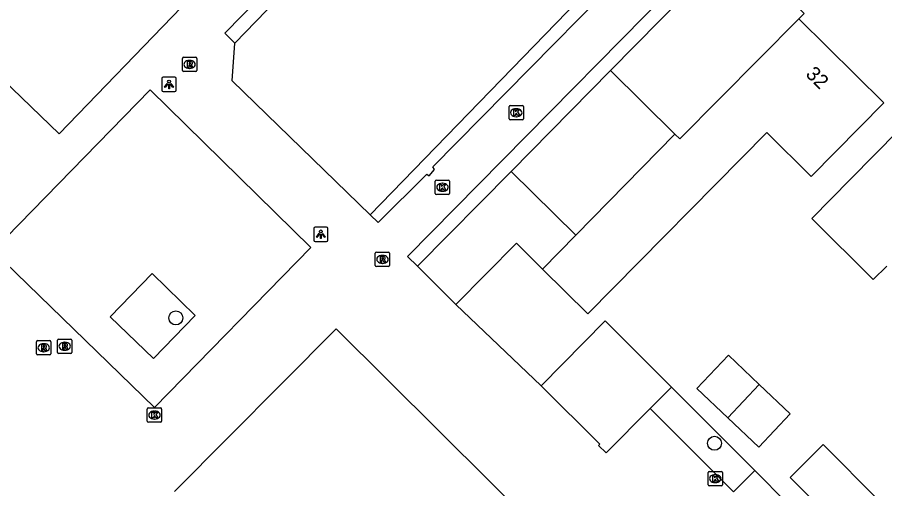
# Model space of a CAD drawing. Extents: x 161772 to 163123, y 383092 to 383917.
# Drawn here: x 162073.6 to 162134.1, y 383301.5 to 383334.4 of the extents above; entities that cross this region are included whole.
import ezdxf

# ---------------------------------------------------------------- set-up
doc = ezdxf.new("R2010")
doc.units = 0
for name, color, linetype in [('IMGEO_Boom', 7, 'Continuous'), ('IMGEO_Erf', 7, 'Continuous'), ('IMGEO_Groenvoorziening', 7, 'Continuous'), ('IMGEO_Kolk', 7, 'Continuous'), ('IMGEO_Lichtpunt', 7, 'Continuous'), ('IMGEO_Pand', 7, 'Continuous'), ('IMGEO_Pand_nummerreeks', 7, 'Continuous'), ('IMGEO_Rijbaan_lokaal_open', 7, 'Continuous'), ('IMGEO_Rioolput', 7, 'Continuous'), ('IMGEO_Voetpad_open', 7, 'Continuous')]:
    doc.layers.add(name, color=color, linetype=linetype)

msp = doc.modelspace()

# ---------------------------------------------------------------- linework, layer by layer
at = {"layer": 'IMGEO_Boom'}
for centre in [(162084.661, 383313.418), (162122.266, 383304.673)]:
    msp.add_circle(centre, 0.489, dxfattribs=at)
at = {"layer": 'IMGEO_Erf'}
msp.add_lwpolyline([(162108.065, 383323.626), (162115.011, 383330.687)], dxfattribs=at)
at = {"layer": 'IMGEO_Groenvoorziening'}
msp.add_lwpolyline([(162125.085, 383302.767), (162119.266, 383308.601)], dxfattribs=at)
at = {"layer": 'IMGEO_Kolk'}
for p, q in [((162107.927, 383327.31), (162107.927, 383328.162)), ((162108.002, 383328.236), (162108.854, 383328.236)), ((162108.415, 383328.016), (162108.44, 383328.016)), ((162108.928, 383328.162), (162108.928, 383327.31)), ((162108.438, 383327.456), (162108.413, 383327.456)), ((162108.854, 383327.236), (162108.002, 383327.236)), ((162102.773, 383322.104), (162102.773, 383322.956)), ((162102.848, 383323.03), (162103.7, 383323.03)), ((162103.261, 383322.81), (162103.286, 383322.81)), ((162103.774, 383322.956), (162103.774, 383322.104)), ((162103.7, 383322.03), (162102.848, 383322.03)), ((162103.284, 383322.25), (162103.259, 383322.25)), ((162082.67, 383306.214), (162082.67, 383307.066)), ((162082.745, 383307.14), (162083.597, 383307.14)), ((162083.158, 383306.92), (162083.183, 383306.92)), ((162083.671, 383307.066), (162083.671, 383306.214)), ((162083.181, 383306.36), (162083.156, 383306.36)), ((162083.597, 383306.14), (162082.745, 383306.14)), ((162121.824, 383301.788), (162121.824, 383302.64)), ((162121.899, 383302.714), (162122.751, 383302.714)), ((162122.825, 383302.64), (162122.825, 383301.788)), ((162122.335, 383301.934), (162122.31, 383301.934)), ((162122.312, 383302.494), (162122.337, 383302.494)), ((162122.751, 383301.714), (162121.899, 383301.714))]:
    msp.add_line(p, q, dxfattribs=at)
for points in [[(162107.927, 383327.31), (162107.927, 383328.162)], [(162108.002, 383328.236), (162108.854, 383328.236)], [(162108.928, 383328.162), (162108.928, 383327.31)], [(162108.248, 383327.936), (162108.371, 383327.936), (162108.371, 383327.785), (162108.501, 383327.936), (162108.665, 383327.936), (162108.519, 383327.785), (162108.672, 383327.536), (162108.52, 383327.536), (162108.435, 383327.7), (162108.371, 383327.633), (162108.371, 383327.536), (162108.248, 383327.536), (162108.248, 383327.936)], [(162108.854, 383327.236), (162108.002, 383327.236)], [(162102.773, 383322.104), (162102.773, 383322.956)], [(162102.848, 383323.03), (162103.7, 383323.03)], [(162103.094, 383322.73), (162103.217, 383322.73), (162103.217, 383322.579), (162103.347, 383322.73), (162103.511, 383322.73), (162103.365, 383322.579), (162103.518, 383322.33), (162103.366, 383322.33), (162103.281, 383322.494), (162103.217, 383322.427), (162103.217, 383322.33), (162103.094, 383322.33), (162103.094, 383322.73)], [(162103.774, 383322.956), (162103.774, 383322.104)], [(162103.7, 383322.03), (162102.848, 383322.03)], [(162082.67, 383306.214), (162082.67, 383307.066)], [(162082.745, 383307.14), (162083.597, 383307.14)], [(162082.991, 383306.84), (162083.114, 383306.84), (162083.114, 383306.689), (162083.244, 383306.84), (162083.408, 383306.84), (162083.262, 383306.689), (162083.415, 383306.44), (162083.263, 383306.44), (162083.178, 383306.604), (162083.114, 383306.537), (162083.114, 383306.44), (162082.991, 383306.44), (162082.991, 383306.84)], [(162083.671, 383307.066), (162083.671, 383306.214)], [(162083.597, 383306.14), (162082.745, 383306.14)], [(162121.824, 383301.788), (162121.824, 383302.64)], [(162121.899, 383302.714), (162122.751, 383302.714)], [(162122.825, 383302.64), (162122.825, 383301.788)], [(162122.145, 383302.414), (162122.268, 383302.414), (162122.268, 383302.263), (162122.398, 383302.414), (162122.562, 383302.414), (162122.416, 383302.263), (162122.569, 383302.014), (162122.417, 383302.014), (162122.332, 383302.178), (162122.268, 383302.111), (162122.268, 383302.014), (162122.145, 383302.014), (162122.145, 383302.414)], [(162122.751, 383301.714), (162121.899, 383301.714)]]:
    msp.add_lwpolyline(points, dxfattribs=at)
for centre, start, end in [((162108.004, 383328.16), 91.55205, 178.44795), ((162108.004, 383328.16), 91.55205, 178.44795), ((162108.852, 383328.16), 1.55205, 88.44795), ((162108.852, 383328.16), 1.55205, 88.44795), ((162108.004, 383327.312), 181.55205, 268.44795), ((162108.004, 383327.312), 181.55205, 268.44795), ((162108.852, 383327.312), 271.55205, 358.44795), ((162108.852, 383327.312), 271.55205, 358.44795), ((162102.85, 383322.954), 91.55205, 178.44795), ((162102.85, 383322.954), 91.55205, 178.44795), ((162103.698, 383322.954), 1.55205, 88.44795), ((162103.698, 383322.954), 1.55205, 88.44795), ((162102.85, 383322.106), 181.55205, 268.44795), ((162102.85, 383322.106), 181.55205, 268.44795), ((162103.698, 383322.106), 271.55205, 358.44795), ((162103.698, 383322.106), 271.55205, 358.44795), ((162082.747, 383307.064), 91.55205, 178.44795), ((162082.747, 383307.064), 91.55205, 178.44795), ((162083.595, 383307.064), 1.55205, 88.44795), ((162083.595, 383307.064), 1.55205, 88.44795), ((162082.747, 383306.216), 181.55205, 268.44795), ((162082.747, 383306.216), 181.55205, 268.44795), ((162083.595, 383306.216), 271.55205, 358.44795), ((162083.595, 383306.216), 271.55205, 358.44795), ((162121.901, 383302.638), 91.55205, 178.44795), ((162121.901, 383302.638), 91.55205, 178.44795), ((162122.749, 383302.638), 1.55205, 88.44795), ((162122.749, 383302.638), 1.55205, 88.44795), ((162121.901, 383301.79), 181.55205, 268.44795), ((162121.901, 383301.79), 181.55205, 268.44795), ((162122.749, 383301.79), 271.55205, 358.44795), ((162122.749, 383301.79), 271.55205, 358.44795)]:
    msp.add_arc(centre, 0.0765, start, end, dxfattribs=at)
for centre, major_axis, ratio, start_param, end_param in [((162108.414, 383327.736), (-0.387, 0.002), 0.722429, 4.712389, 7.853982), ((162108.439, 383327.736), (-0.39, 0.002), 0.717154, 1.570796, 4.712389), ((162103.26, 383322.53), (-0.387, 0.002), 0.722429, 4.712389, 7.853982), ((162103.285, 383322.53), (-0.39, 0.002), 0.717154, 1.570796, 4.712389), ((162083.157, 383306.64), (-0.387, 0.002), 0.722429, 4.712389, 7.853982), ((162083.182, 383306.64), (-0.39, 0.002), 0.717154, 1.570796, 4.712389), ((162122.311, 383302.214), (-0.387, 0.002), 0.722429, 4.712389, 7.853982), ((162122.336, 383302.214), (-0.39, 0.002), 0.717154, 1.570796, 4.712389)]:
    msp.add_ellipse(centre, major_axis=major_axis, ratio=ratio, start_param=start_param, end_param=end_param, dxfattribs=at)
at = {"layer": 'IMGEO_Lichtpunt'}
for p, q in [((162083.687, 383330.115), (162083.687, 383329.308)), ((162083.687, 383330.115), (162083.687, 383329.308)), ((162084.589, 383330.21), (162083.781, 383330.21)), ((162084.589, 383330.21), (162083.781, 383330.21)), ((162084.683, 383329.308), (162084.683, 383330.115)), ((162084.683, 383329.308), (162084.683, 383330.115)), ((162083.781, 383329.214), (162084.589, 383329.214)), ((162083.781, 383329.214), (162084.589, 383329.214)), ((162094.286, 383319.656), (162094.286, 383318.849)), ((162094.286, 383319.656), (162094.286, 383318.849)), ((162095.188, 383319.751), (162094.38, 383319.751)), ((162095.188, 383319.751), (162094.38, 383319.751)), ((162095.282, 383318.849), (162095.282, 383319.656)), ((162095.282, 383318.849), (162095.282, 383319.656)), ((162094.38, 383318.755), (162095.188, 383318.755)), ((162094.38, 383318.755), (162095.188, 383318.755))]:
    msp.add_line(p, q, dxfattribs=at)
for points in [[(162084.061, 383329.779), (162084.1, 383329.751), (162083.912, 383329.489), (162083.874, 383329.516), (162084.061, 383329.779)], [(162084.273, 383329.751), (162084.311, 383329.778), (162084.498, 383329.516), (162084.459, 383329.488), (162084.273, 383329.751)], [(162084.163, 383329.731), (162084.21, 383329.731), (162084.21, 383329.409), (162084.163, 383329.409), (162084.163, 383329.731)], [(162094.66, 383319.32), (162094.699, 383319.292), (162094.511, 383319.03), (162094.473, 383319.057), (162094.66, 383319.32)], [(162094.762, 383319.272), (162094.809, 383319.272), (162094.809, 383318.95), (162094.762, 383318.95), (162094.762, 383319.272)], [(162094.872, 383319.292), (162094.91, 383319.319), (162095.097, 383319.057), (162095.058, 383319.029), (162094.872, 383319.292)]]:
    msp.add_lwpolyline(points, dxfattribs=at)
for centre in [(162084.186, 383329.913), (162094.785, 383319.454)]:
    msp.add_circle(centre, 0.0994, dxfattribs=at)
for centre, start, end in [((162083.781, 383330.115), 90, 180), ((162083.781, 383330.115), 90, 180), ((162084.589, 383330.115), 0, 90), ((162084.589, 383330.115), 0, 90), ((162083.781, 383329.308), 180, 270), ((162083.781, 383329.308), 180, 270), ((162084.589, 383329.308), 270, 0), ((162084.589, 383329.308), 270, 360), ((162094.38, 383319.656), 90, 180), ((162094.38, 383319.656), 90, 180), ((162095.188, 383319.656), 0, 90), ((162095.188, 383319.656), 0, 90), ((162094.38, 383318.849), 180, 270), ((162094.38, 383318.849), 180, 270), ((162095.188, 383318.849), 270, 0), ((162095.188, 383318.849), 270, 360)]:
    msp.add_arc(centre, 0.0946, start, end, dxfattribs=at)
at = {"layer": 'IMGEO_Pand'}
for points in [[(162088.781, 383332.589), (162104.911, 383349.231), (162115.766, 383338.708)], [(162115.011, 383330.687), (162123.664, 383339.476), (162128.52, 383334.645), (162128.16, 383334.283)], [(162115.766, 383338.708), (162098.225, 383320.611)], [(162128.16, 383334.283), (162134.092, 383328.422), (162129.012, 383323.283), (162125.92, 383326.354), (162113.418, 383313.706), (162110.271, 383316.822)], [(162128.16, 383334.283), (162119.841, 383325.918), (162119.51, 383326.245)], [(162098.225, 383320.611), (162088.594, 383329.946), (162088.781, 383332.589)], [(162119.51, 383326.245), (162115.011, 383330.687)], [(162134.301, 383317.03), (162133.351, 383316.108), (162129.054, 383320.347), (162131.763, 383323.094), (162136.795, 383328.196), (162141.151, 383323.9), (162141.014, 383323.761)], [(162112.592, 383319.189), (162119.51, 383326.245)], [(162101.529, 383317.021), (162108.065, 383323.626)], [(162112.592, 383319.189), (162108.065, 383323.626)], [(162110.271, 383316.822), (162112.592, 383319.189)], [(162110.271, 383316.822), (162108.445, 383318.63), (162104.216, 383314.348)], [(162101.529, 383317.021), (162104.216, 383314.348)], [(162110.161, 383308.679), (162114.631, 383313.211), (162119.266, 383308.601)], [(162113.782, 383294.862), (162095.853, 383312.658), (162084.572, 383301.309)], [(162123.197, 383306.442), (162121.038, 383308.485), (162123.238, 383310.81), (162125.398, 383308.767)], [(162110.161, 383308.679), (162114.271, 383304.622), (162114.18, 383304.529), (162114.711, 383304.006), (162117.787, 383307.109)], [(162119.266, 383308.601), (162117.787, 383307.109)], [(162125.398, 383308.767), (162127.557, 383306.724), (162125.357, 383304.399), (162123.197, 383306.442)], [(162125.398, 383308.767), (162123.197, 383306.442)], [(162131.74, 383298.082), (162127.54, 383302.293), (162129.848, 383304.595), (162133.741, 383300.691), (162133.453, 383300.404), (162133.743, 383300.114)]]:
    msp.add_lwpolyline(points, dxfattribs=at)
at = {"layer": 'IMGEO_Rijbaan_lokaal_open'}
for points in [[(162111.39, 383357.056), (162088.084, 383333.272), (162088.781, 383332.589)], [(162098.225, 383320.611), (162098.776, 383320.077), (162102.187, 383323.44), (162102.34, 383323.339), (162102.713, 383323.781), (162102.606, 383323.956), (162121.251, 383342.87)], [(162125.72, 383342.934), (162100.83, 383317.698), (162101.529, 383317.021)], [(162072.586, 383330.051), (162076.509, 383326.257), (162085.05, 383335.095)], [(162082.872, 383329.333), (162071.894, 383318.107), (162083.161, 383307.175), (162094.093, 383318.339), (162082.872, 383329.333)], [(162104.216, 383314.348), (162110.161, 383308.679)], [(162117.787, 383307.109), (162123.599, 383301.284), (162125.085, 383302.767)], [(162125.085, 383302.767), (162127.351, 383300.496)]]:
    msp.add_lwpolyline(points, dxfattribs=at)
at = {"layer": 'IMGEO_Rioolput'}
for p, q in [((162085.195, 383331.6), (162086.047, 383331.6)), ((162085.12, 383330.674), (162085.12, 383331.526)), ((162085.608, 383331.38), (162085.633, 383331.38)), ((162086.121, 383331.526), (162086.121, 383330.674)), ((162086.047, 383330.6), (162085.195, 383330.6)), ((162085.631, 383330.82), (162085.606, 383330.82)), ((162098.586, 383317.079), (162098.586, 383317.931)), ((162098.661, 383318.005), (162099.513, 383318.005)), ((162099.074, 383317.785), (162099.099, 383317.785)), ((162099.587, 383317.931), (162099.587, 383317.079)), ((162099.097, 383317.225), (162099.072, 383317.225)), ((162099.513, 383317.005), (162098.661, 383317.005)), ((162074.935, 383310.911), (162074.935, 383311.763)), ((162075.01, 383311.837), (162075.862, 383311.837)), ((162075.423, 383311.617), (162075.448, 383311.617)), ((162075.936, 383311.763), (162075.936, 383310.911)), ((162076.403, 383311.016), (162076.403, 383311.868)), ((162076.478, 383311.942), (162077.33, 383311.942)), ((162076.891, 383311.722), (162076.916, 383311.722)), ((162077.404, 383311.868), (162077.404, 383311.016)), ((162075.446, 383311.057), (162075.421, 383311.057)), ((162076.914, 383311.162), (162076.889, 383311.162)), ((162075.862, 383310.837), (162075.01, 383310.837)), ((162077.33, 383310.942), (162076.478, 383310.942))]:
    msp.add_line(p, q, dxfattribs=at)
for points in [[(162085.195, 383331.6), (162086.047, 383331.6)], [(162085.12, 383330.674), (162085.12, 383331.526)], [(162085.709, 383331.298), (162085.457, 383331.3), (162085.457, 383330.9)], [(162085.457, 383330.9), (162085.581, 383330.9), (162085.581, 383331.062), (162085.592, 383331.062)], [(162085.635, 383331.219), (162085.581, 383331.219), (162085.581, 383331.138)], [(162085.581, 383331.138), (162085.633, 383331.138)], [(162085.639, 383331.033), (162085.71, 383330.9), (162085.85, 383330.9), (162085.785, 383331.026)], [(162086.121, 383331.526), (162086.121, 383330.674)], [(162086.047, 383330.6), (162085.195, 383330.6)], [(162098.586, 383317.079), (162098.586, 383317.931)], [(162098.661, 383318.005), (162099.513, 383318.005)], [(162099.175, 383317.703), (162098.923, 383317.705), (162098.923, 383317.305)], [(162099.587, 383317.931), (162099.587, 383317.079)], [(162098.923, 383317.305), (162099.047, 383317.305), (162099.047, 383317.467), (162099.058, 383317.467)], [(162099.101, 383317.624), (162099.047, 383317.624), (162099.047, 383317.543)], [(162099.047, 383317.543), (162099.099, 383317.543)], [(162099.105, 383317.438), (162099.176, 383317.305), (162099.316, 383317.305), (162099.251, 383317.431)], [(162099.513, 383317.005), (162098.661, 383317.005)], [(162074.935, 383310.911), (162074.935, 383311.763)], [(162075.01, 383311.837), (162075.862, 383311.837)], [(162075.936, 383311.763), (162075.936, 383310.911)], [(162076.403, 383311.016), (162076.403, 383311.868)], [(162076.478, 383311.942), (162077.33, 383311.942)], [(162076.992, 383311.64), (162076.74, 383311.642), (162076.74, 383311.242)], [(162077.404, 383311.868), (162077.404, 383311.016)], [(162075.524, 383311.535), (162075.272, 383311.537), (162075.272, 383311.137)], [(162075.272, 383311.137), (162075.396, 383311.137), (162075.396, 383311.299), (162075.407, 383311.299)], [(162075.45, 383311.456), (162075.396, 383311.456), (162075.396, 383311.375)], [(162075.396, 383311.375), (162075.448, 383311.375)], [(162075.454, 383311.27), (162075.525, 383311.137), (162075.665, 383311.137), (162075.6, 383311.263)], [(162076.74, 383311.242), (162076.864, 383311.242), (162076.864, 383311.404), (162076.875, 383311.404)], [(162076.918, 383311.561), (162076.864, 383311.561), (162076.864, 383311.48)], [(162076.864, 383311.48), (162076.916, 383311.48)], [(162076.922, 383311.375), (162076.993, 383311.242), (162077.133, 383311.242), (162077.068, 383311.368)], [(162075.862, 383310.837), (162075.01, 383310.837)], [(162077.33, 383310.942), (162076.478, 383310.942)]]:
    msp.add_lwpolyline(points, dxfattribs=at)
for centre, radius, start, end in [((162085.197, 383331.524), 0.0765, 91.55205, 178.44795), ((162085.197, 383331.524), 0.0765, 91.55205, 178.44795), ((162086.045, 383331.524), 0.0765, 1.55205, 88.44795), ((162086.045, 383331.524), 0.0765, 1.55205, 88.44795), ((162085.591, 383331.009), 0.0533, 26.02933, 88.69889), ((162085.617, 383331.327), 0.19, 274.7715, 282.96867), ((162085.641, 383331.123), 0.0964, 77.00612, 93.18647), ((162085.655, 383331.18), 0.0378, 276.66336, 79.67722), ((162085.708, 383331.188), 0.109, 350.36119, 89.41601), ((162085.706, 383331.188), 0.112, 277.58423, 350.98172), ((162085.69, 383330.973), 0.108, 29.51342, 73.79051), ((162085.197, 383330.676), 0.0765, 181.55205, 268.44795), ((162085.197, 383330.676), 0.0765, 181.55205, 268.44795), ((162086.045, 383330.676), 0.0765, 271.55205, 358.44795), ((162086.045, 383330.676), 0.0765, 271.55205, 358.44795), ((162098.663, 383317.929), 0.0765, 91.55205, 178.44795), ((162098.663, 383317.929), 0.0765, 91.55205, 178.44795), ((162099.174, 383317.593), 0.109, 350.36119, 89.41601), ((162099.511, 383317.929), 0.0765, 1.55205, 88.44795), ((162099.511, 383317.929), 0.0765, 1.55205, 88.44795), ((162098.663, 383317.081), 0.0765, 181.55205, 268.44795), ((162098.663, 383317.081), 0.0765, 181.55205, 268.44795), ((162099.057, 383317.414), 0.0533, 26.02933, 88.69889), ((162099.083, 383317.732), 0.19, 274.7715, 282.96867), ((162099.107, 383317.528), 0.0964, 77.00612, 93.18647), ((162099.121, 383317.585), 0.0378, 276.66336, 79.67722), ((162099.172, 383317.593), 0.112, 277.58423, 350.98172), ((162099.156, 383317.378), 0.108, 29.51342, 73.79051), ((162099.511, 383317.081), 0.0765, 271.55205, 358.44795), ((162099.511, 383317.081), 0.0765, 271.55205, 358.44795), ((162075.012, 383311.761), 0.0765, 91.55205, 178.44795), ((162075.012, 383311.761), 0.0765, 91.55205, 178.44795), ((162075.86, 383311.761), 0.0765, 1.55205, 88.44795), ((162075.86, 383311.761), 0.0765, 1.55205, 88.44795), ((162076.48, 383311.866), 0.0765, 91.55205, 178.44795), ((162076.48, 383311.866), 0.0765, 91.55205, 178.44795), ((162076.991, 383311.53), 0.109, 350.36119, 89.41601), ((162077.328, 383311.866), 0.0765, 1.55205, 88.44795), ((162077.328, 383311.866), 0.0765, 1.55205, 88.44795), ((162075.406, 383311.246), 0.0533, 26.02933, 88.69889), ((162075.432, 383311.564), 0.19, 274.7715, 282.96867), ((162075.456, 383311.36), 0.0964, 77.00612, 93.18647), ((162075.47, 383311.417), 0.0378, 276.66336, 79.67722), ((162075.523, 383311.425), 0.109, 350.36119, 89.41601), ((162075.521, 383311.425), 0.112, 277.58423, 350.98172), ((162075.505, 383311.21), 0.108, 29.51342, 73.79051), ((162076.48, 383311.018), 0.0765, 181.55205, 268.44795), ((162076.48, 383311.018), 0.0765, 181.55205, 268.44795), ((162076.874, 383311.351), 0.0533, 26.02933, 88.69889), ((162076.9, 383311.669), 0.19, 274.7715, 282.96867), ((162076.924, 383311.465), 0.0964, 77.00612, 93.18647), ((162076.938, 383311.522), 0.0378, 276.66336, 79.67722), ((162076.989, 383311.53), 0.112, 277.58423, 350.98172), ((162076.973, 383311.315), 0.108, 29.51342, 73.79051), ((162077.328, 383311.018), 0.0765, 271.55205, 358.44795), ((162077.328, 383311.018), 0.0765, 271.55205, 358.44795), ((162075.012, 383310.913), 0.0765, 181.55205, 268.44795), ((162075.012, 383310.913), 0.0765, 181.55205, 268.44795), ((162075.86, 383310.913), 0.0765, 271.55205, 358.44795), ((162075.86, 383310.913), 0.0765, 271.55205, 358.44795)]:
    msp.add_arc(centre, radius, start, end, dxfattribs=at)
for centre, major_axis, ratio, start_param, end_param in [((162085.607, 383331.1), (-0.387, 0.002), 0.722429, 4.712389, 7.853982), ((162085.632, 383331.1), (-0.39, 0.002), 0.717154, 1.570796, 4.712389), ((162099.073, 383317.505), (-0.387, 0.002), 0.722429, 4.712389, 7.853982), ((162099.098, 383317.505), (-0.39, 0.002), 0.717154, 1.570796, 4.712389), ((162075.422, 383311.337), (-0.387, 0.002), 0.722429, 4.712389, 7.853982), ((162075.447, 383311.337), (-0.39, 0.002), 0.717154, 1.570796, 4.712389), ((162076.89, 383311.442), (-0.387, 0.002), 0.722429, 4.712389, 7.853982), ((162076.915, 383311.442), (-0.39, 0.002), 0.717154, 1.570796, 4.712389)]:
    msp.add_ellipse(centre, major_axis=major_axis, ratio=ratio, start_param=start_param, end_param=end_param, dxfattribs=at)
at = {"layer": 'IMGEO_Voetpad_open'}
msp.add_lwpolyline([(162080.081, 383313.507), (162083.095, 383310.583), (162086.02, 383313.597), (162083.006, 383316.522), (162080.081, 383313.507)], dxfattribs=at)

# ---------------------------------------------------------------- texts
at = {"layer": 'IMGEO_Pand_nummerreeks'}
msp.add_text('32', height=1, rotation=315.34367, dxfattribs=at).set_placement((162128.575, 383330.359))

doc.saveas('drawing.dxf')
